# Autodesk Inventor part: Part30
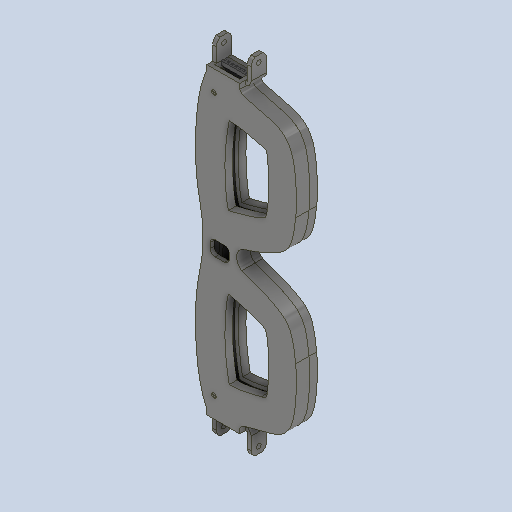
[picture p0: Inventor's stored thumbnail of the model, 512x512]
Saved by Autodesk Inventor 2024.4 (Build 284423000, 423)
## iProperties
Created: 2025-05
Part Number: Part30
Material: Generic
Document SubType Name: Modeling
Designer: AdminForWorker
Density: 1 g/cm^3
Appearance: Default
Author: AdminForWorker
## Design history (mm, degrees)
feature "Base layer" [Body]
feature "Body39"
feature "Body50"
feature "Body51"
body "Solid1"
body "Solid2"
body "Solid3"
body "Solid4"
